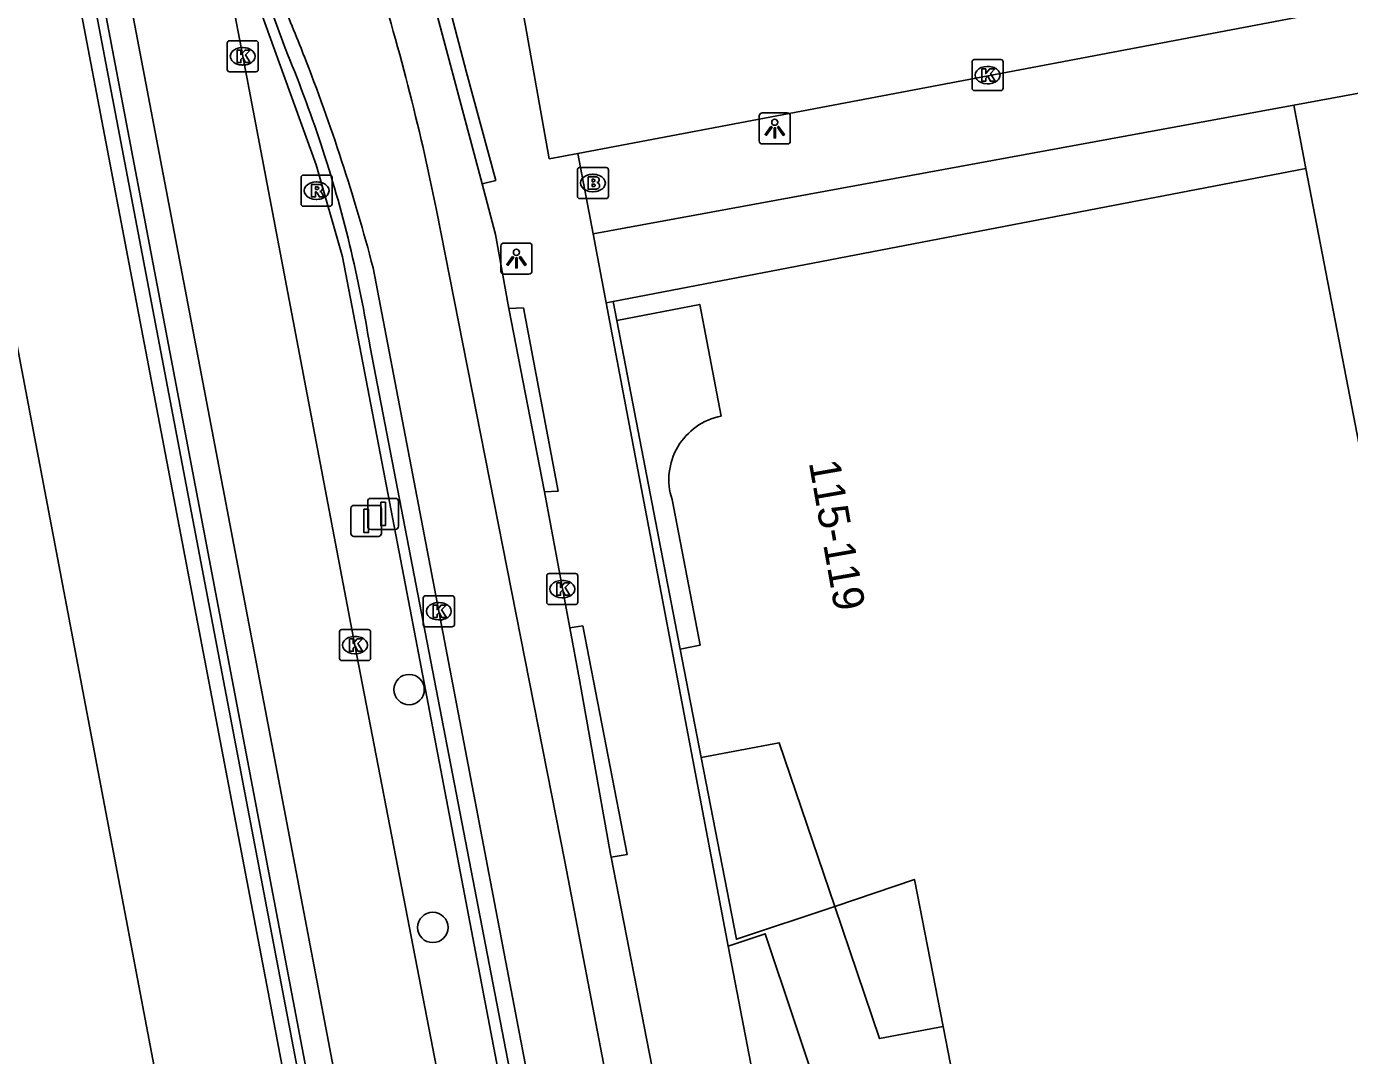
# Model space of a CAD drawing. Extents: x 159265 to 160143, y 383413 to 384319.
# Drawn here: x 159294.72 to 159337.31, y 383838.39 to 383871.52 of the extents above; entities that cross this region are included whole.
import ezdxf

# ---------------------------------------------------------------- set-up
doc = ezdxf.new("R2010")
doc.units = 0
for name, color, linetype in [('IMGEO_Boom', 7, 'Continuous'), ('IMGEO_Brandkraan', 7, 'Continuous'), ('IMGEO_Haag', 7, 'Continuous'), ('IMGEO_Kolk', 7, 'Continuous'), ('IMGEO_Lichtpunt', 7, 'Continuous'), ('IMGEO_Lijnafwatering', 7, 'Continuous'), ('IMGEO_Muur', 7, 'Continuous'), ('IMGEO_Pand', 7, 'Continuous'), ('IMGEO_Pand_nummerreeks', 7, 'Continuous'), ('IMGEO_Pand_overbouw', 7, 'Continuous'), ('IMGEO_Rijbaan_lokaal_gesloten', 7, 'Continuous'), ('IMGEO_Rijbaan_lokaal_open', 7, 'Continuous'), ('IMGEO_Rijbaan_regionaal_gesloten', 7, 'Continuous'), ('IMGEO_Rioolput', 7, 'Continuous'), ('IMGEO_Verkeersbordpaal', 7, 'Continuous'), ('IMGEO_Voetpad_open', 7, 'Continuous')]:
    doc.layers.add(name, color=color, linetype=linetype)

msp = doc.modelspace()

# ---------------------------------------------------------------- linework, layer by layer
at = {"layer": 'IMGEO_Boom'}
for centre in [(159307.041, 383850.169), (159307.803, 383842.511)]:
    msp.add_circle(centre, 0.489, dxfattribs=at)
at = {"layer": 'IMGEO_Brandkraan'}
for p, q in [((159312.456, 383866.053), (159312.456, 383866.905)), ((159312.531, 383866.979), (159313.383, 383866.979)), ((159313.457, 383866.905), (159313.457, 383866.053)), ((159312.944, 383866.759), (159312.969, 383866.759)), ((159313.383, 383865.979), (159312.531, 383865.979)), ((159312.967, 383866.199), (159312.942, 383866.199))]:
    msp.add_line(p, q, dxfattribs=at)
for points in [[(159312.456, 383866.053), (159312.456, 383866.905)], [(159312.531, 383866.979), (159313.383, 383866.979)], [(159313.457, 383866.905), (159313.457, 383866.053)], [(159312.804, 383866.679), (159312.804, 383866.279), (159313.017, 383866.279)], [(159313.035, 383866.679), (159312.804, 383866.679)], [(159312.983, 383866.598), (159312.929, 383866.598), (159312.929, 383866.522)], [(159312.929, 383866.522), (159312.982, 383866.522)], [(159312.991, 383866.446), (159312.929, 383866.446), (159312.929, 383866.365)], [(159313.383, 383865.979), (159312.531, 383865.979)], [(159312.929, 383866.365), (159312.991, 383866.365)]]:
    msp.add_lwpolyline(points, dxfattribs=at)
for centre, radius, start, end in [((159312.533, 383866.903), 0.0765, 91.552, 178.448), ((159312.533, 383866.903), 0.0765, 91.552, 178.448), ((159313.381, 383866.903), 0.0765, 1.552, 88.448), ((159313.381, 383866.903), 0.0765, 1.552, 88.448), ((159312.984, 383866.56), 0.0379, 267.8285, 90.9355), ((159312.992, 383866.405), 0.0404, 269.8759, 90.5077), ((159313.039, 383866.534), 0.145, 59.4692, 91.5367), ((159313.064, 383866.581), 0.0922, 285.5137, 58.1501), ((159313.069, 383866.389), 0.105, 301.3115, 78.989), ((159312.533, 383866.055), 0.0765, 181.552, 268.448), ((159312.533, 383866.055), 0.0765, 181.552, 268.448), ((159313.023, 383866.53), 0.251, 268.6676, 293.5347), ((159313.381, 383866.055), 0.0765, 271.552, 358.448), ((159313.381, 383866.055), 0.0765, 271.552, 358.448)]:
    msp.add_arc(centre, radius, start, end, dxfattribs=at)
for centre, major_axis, ratio, start_param, end_param in [((159312.943, 383866.479), (-0.387, 0.002), 0.722429, 4.712389, 7.853982), ((159312.968, 383866.479), (-0.39, 0.002), 0.717154, 1.570796, 4.712389)]:
    msp.add_ellipse(centre, major_axis=major_axis, ratio=ratio, start_param=start_param, end_param=end_param, dxfattribs=at)
at = {"layer": 'IMGEO_Haag'}
for points in [[(159303.045, 383870.823), (159301.691, 383874.543), (159301.384, 383874.434), (159304.05, 383867.063), (159304.897, 383864.099), (159307.114, 383852.521), (159310.388, 383835.369), (159314.42, 383814.315), (159315.234, 383809.973), (159313.799, 383809.591), (159322.047, 383766.911), (159322.585, 383766.955), (159315.649, 383810.084)], [(159315.649, 383810.084), (159305.782, 383861.189)]]:
    msp.add_lwpolyline(points, dxfattribs=at)
for centre, radius, start, end in [((159264.432, 383854.612), 41.878, 18.2647, 22.7741), ((159264.751, 383854.741), 41.535, 8.931, 18.2339)]:
    msp.add_arc(centre, radius, start, end, dxfattribs=at)
at = {"layer": 'IMGEO_Kolk'}
for p, q in [((159301.183, 383870.133), (159301.183, 383870.985)), ((159301.258, 383871.059), (159302.11, 383871.059)), ((159301.671, 383870.839), (159301.696, 383870.839)), ((159302.184, 383870.985), (159302.184, 383870.133)), ((159301.694, 383870.279), (159301.669, 383870.279)), ((159325.161, 383869.528), (159325.161, 383870.38)), ((159325.236, 383870.454), (159326.088, 383870.454)), ((159325.649, 383870.234), (159325.674, 383870.234)), ((159326.162, 383870.38), (159326.162, 383869.528)), ((159302.11, 383870.059), (159301.258, 383870.059)), ((159326.088, 383869.454), (159325.236, 383869.454)), ((159325.672, 383869.674), (159325.647, 383869.674)), ((159311.471, 383852.979), (159311.471, 383853.831)), ((159311.546, 383853.905), (159312.398, 383853.905)), ((159311.959, 383853.685), (159311.984, 383853.685)), ((159312.472, 383853.831), (159312.472, 383852.979)), ((159307.571, 383853.19), (159308.423, 383853.19)), ((159307.496, 383852.264), (159307.496, 383853.116)), ((159307.984, 383852.97), (159308.009, 383852.97)), ((159308.497, 383853.116), (159308.497, 383852.264)), ((159312.398, 383852.905), (159311.546, 383852.905)), ((159311.982, 383853.125), (159311.957, 383853.125)), ((159308.007, 383852.41), (159307.982, 383852.41)), ((159304.798, 383851.175), (159304.798, 383852.027)), ((159304.873, 383852.101), (159305.725, 383852.101)), ((159305.799, 383852.027), (159305.799, 383851.175)), ((159308.423, 383852.19), (159307.571, 383852.19)), ((159305.286, 383851.881), (159305.311, 383851.881)), ((159305.725, 383851.101), (159304.873, 383851.101)), ((159305.309, 383851.321), (159305.284, 383851.321))]:
    msp.add_line(p, q, dxfattribs=at)
for points in [[(159301.183, 383870.133), (159301.183, 383870.985)], [(159301.258, 383871.059), (159302.11, 383871.059)], [(159301.504, 383870.759), (159301.627, 383870.759), (159301.627, 383870.608), (159301.757, 383870.759), (159301.921, 383870.759), (159301.775, 383870.608), (159301.928, 383870.359), (159301.776, 383870.359), (159301.691, 383870.523), (159301.627, 383870.456), (159301.627, 383870.359), (159301.504, 383870.359), (159301.504, 383870.759)], [(159302.184, 383870.985), (159302.184, 383870.133)], [(159325.161, 383869.528), (159325.161, 383870.38)], [(159325.236, 383870.454), (159326.088, 383870.454)], [(159326.162, 383870.38), (159326.162, 383869.528)], [(159302.11, 383870.059), (159301.258, 383870.059)], [(159325.482, 383870.154), (159325.605, 383870.154), (159325.605, 383870.003), (159325.735, 383870.154), (159325.899, 383870.154), (159325.753, 383870.003), (159325.906, 383869.754), (159325.754, 383869.754), (159325.669, 383869.918), (159325.605, 383869.851), (159325.605, 383869.754), (159325.482, 383869.754), (159325.482, 383870.154)], [(159326.088, 383869.454), (159325.236, 383869.454)], [(159311.471, 383852.979), (159311.471, 383853.831)], [(159311.546, 383853.905), (159312.398, 383853.905)], [(159312.472, 383853.831), (159312.472, 383852.979)], [(159307.571, 383853.19), (159308.423, 383853.19)], [(159311.792, 383853.605), (159311.915, 383853.605), (159311.915, 383853.454), (159312.045, 383853.605), (159312.209, 383853.605), (159312.063, 383853.454), (159312.216, 383853.205), (159312.064, 383853.205), (159311.979, 383853.369), (159311.915, 383853.302), (159311.915, 383853.205), (159311.792, 383853.205), (159311.792, 383853.605)], [(159307.496, 383852.264), (159307.496, 383853.116)], [(159307.817, 383852.89), (159307.94, 383852.89), (159307.94, 383852.739), (159308.07, 383852.89), (159308.234, 383852.89), (159308.088, 383852.739), (159308.241, 383852.49), (159308.089, 383852.49), (159308.004, 383852.654), (159307.94, 383852.587), (159307.94, 383852.49), (159307.817, 383852.49), (159307.817, 383852.89)], [(159308.497, 383853.116), (159308.497, 383852.264)], [(159312.398, 383852.905), (159311.546, 383852.905)], [(159304.798, 383851.175), (159304.798, 383852.027)], [(159304.873, 383852.101), (159305.725, 383852.101)], [(159305.799, 383852.027), (159305.799, 383851.175)], [(159308.423, 383852.19), (159307.571, 383852.19)], [(159305.119, 383851.801), (159305.242, 383851.801), (159305.242, 383851.65), (159305.372, 383851.801), (159305.536, 383851.801), (159305.39, 383851.65), (159305.543, 383851.401), (159305.391, 383851.401), (159305.306, 383851.565), (159305.242, 383851.498), (159305.242, 383851.401), (159305.119, 383851.401), (159305.119, 383851.801)], [(159305.725, 383851.101), (159304.873, 383851.101)]]:
    msp.add_lwpolyline(points, dxfattribs=at)
for centre, start, end in [((159301.26, 383870.983), 91.552, 178.448), ((159301.26, 383870.983), 91.552, 178.448), ((159302.108, 383870.983), 1.552, 88.448), ((159302.108, 383870.983), 1.552, 88.448), ((159325.238, 383870.378), 91.552, 178.448), ((159325.238, 383870.378), 91.552, 178.448), ((159326.086, 383870.378), 1.552, 88.448), ((159326.086, 383870.378), 1.552, 88.448), ((159301.26, 383870.135), 181.552, 268.448), ((159301.26, 383870.135), 181.552, 268.448), ((159302.108, 383870.135), 271.552, 358.448), ((159302.108, 383870.135), 271.552, 358.448), ((159325.238, 383869.53), 181.552, 268.448), ((159325.238, 383869.53), 181.552, 268.448), ((159326.086, 383869.53), 271.552, 358.448), ((159326.086, 383869.53), 271.552, 358.448), ((159311.548, 383853.829), 91.552, 178.448), ((159311.548, 383853.829), 91.552, 178.448), ((159312.396, 383853.829), 1.552, 88.448), ((159312.396, 383853.829), 1.552, 88.448), ((159307.573, 383853.114), 91.552, 178.448), ((159307.573, 383853.114), 91.552, 178.448), ((159308.421, 383853.114), 1.552, 88.448), ((159308.421, 383853.114), 1.552, 88.448), ((159311.548, 383852.981), 181.552, 268.448), ((159311.548, 383852.981), 181.552, 268.448), ((159312.396, 383852.981), 271.552, 358.448), ((159312.396, 383852.981), 271.552, 358.448), ((159304.875, 383852.025), 91.552, 178.448), ((159304.875, 383852.025), 91.552, 178.448), ((159305.723, 383852.025), 1.552, 88.448), ((159305.723, 383852.025), 1.552, 88.448), ((159307.573, 383852.266), 181.552, 268.448), ((159307.573, 383852.266), 181.552, 268.448), ((159308.421, 383852.266), 271.552, 358.448), ((159308.421, 383852.266), 271.552, 358.448), ((159304.875, 383851.177), 181.552, 268.448), ((159304.875, 383851.177), 181.552, 268.448), ((159305.723, 383851.177), 271.552, 358.448), ((159305.723, 383851.177), 271.552, 358.448)]:
    msp.add_arc(centre, 0.0765, start, end, dxfattribs=at)
for centre, major_axis, ratio, start_param, end_param in [((159301.67, 383870.559), (-0.387, 0.002), 0.722429, 4.712389, 7.853982), ((159301.695, 383870.559), (-0.39, 0.002), 0.717154, 1.570796, 4.712389), ((159325.648, 383869.954), (-0.387, 0.002), 0.722429, 4.712389, 7.853982), ((159325.673, 383869.954), (-0.39, 0.002), 0.717154, 1.570796, 4.712389), ((159311.958, 383853.405), (-0.387, 0.002), 0.722429, 4.712389, 7.853982), ((159311.983, 383853.405), (-0.39, 0.002), 0.717154, 1.570796, 4.712389), ((159307.983, 383852.69), (-0.387, 0.002), 0.722429, 4.712389, 7.853982), ((159308.008, 383852.69), (-0.39, 0.002), 0.717154, 1.570796, 4.712389), ((159305.285, 383851.601), (-0.387, 0.002), 0.722429, 4.712389, 7.853982), ((159305.31, 383851.601), (-0.39, 0.002), 0.717154, 1.570796, 4.712389)]:
    msp.add_ellipse(centre, major_axis=major_axis, ratio=ratio, start_param=start_param, end_param=end_param, dxfattribs=at)
at = {"layer": 'IMGEO_Lichtpunt'}
for p, q in [((159318.313, 383868.639), (159318.313, 383867.832)), ((159318.313, 383868.639), (159318.313, 383867.832)), ((159319.215, 383868.734), (159318.407, 383868.734)), ((159319.215, 383868.734), (159318.407, 383868.734)), ((159319.309, 383867.832), (159319.309, 383868.639)), ((159319.309, 383867.832), (159319.309, 383868.639)), ((159318.407, 383867.738), (159319.215, 383867.738)), ((159318.407, 383867.738), (159319.215, 383867.738)), ((159309.997, 383864.45), (159309.997, 383863.643)), ((159309.997, 383864.45), (159309.997, 383863.643)), ((159310.899, 383864.545), (159310.091, 383864.545)), ((159310.899, 383864.545), (159310.091, 383864.545)), ((159310.993, 383863.643), (159310.993, 383864.45)), ((159310.993, 383863.643), (159310.993, 383864.45)), ((159310.091, 383863.549), (159310.899, 383863.549)), ((159310.091, 383863.549), (159310.899, 383863.549))]:
    msp.add_line(p, q, dxfattribs=at)
for points in [[(159318.687, 383868.303), (159318.726, 383868.275), (159318.538, 383868.013), (159318.5, 383868.04), (159318.687, 383868.303)], [(159318.789, 383868.255), (159318.836, 383868.255), (159318.836, 383867.933), (159318.789, 383867.933), (159318.789, 383868.255)], [(159318.899, 383868.275), (159318.937, 383868.302), (159319.124, 383868.04), (159319.085, 383868.012), (159318.899, 383868.275)], [(159310.371, 383864.114), (159310.41, 383864.086), (159310.222, 383863.824), (159310.184, 383863.851), (159310.371, 383864.114)], [(159310.473, 383864.066), (159310.52, 383864.066), (159310.52, 383863.744), (159310.473, 383863.744), (159310.473, 383864.066)], [(159310.583, 383864.086), (159310.621, 383864.113), (159310.808, 383863.851), (159310.769, 383863.823), (159310.583, 383864.086)]]:
    msp.add_lwpolyline(points, dxfattribs=at)
for centre in [(159318.812, 383868.437), (159310.496, 383864.248)]:
    msp.add_circle(centre, 0.0994, dxfattribs=at)
for centre, start, end in [((159318.407, 383868.639), 90, 180), ((159318.407, 383868.639), 90, 180), ((159319.215, 383868.639), 0, 90), ((159319.215, 383868.639), 0, 90), ((159318.407, 383867.832), 180, 270), ((159318.407, 383867.832), 180, 270), ((159319.215, 383867.832), 270, 0), ((159319.215, 383867.832), 270, 360), ((159310.091, 383864.45), 90, 180), ((159310.091, 383864.45), 90, 180), ((159310.899, 383864.45), 0, 90), ((159310.899, 383864.45), 0, 90), ((159310.091, 383863.643), 180, 270), ((159310.091, 383863.643), 180, 270), ((159310.899, 383863.643), 270, 0), ((159310.899, 383863.643), 270, 360)]:
    msp.add_arc(centre, 0.0946, start, end, dxfattribs=at)
at = {"layer": 'IMGEO_Lijnafwatering'}
for points in [[(159294.994, 383879.804), (159298.74, 383860.158)], [(159298.74, 383860.158), (159302.502, 383840.43)], [(159302.502, 383840.43), (159306.23, 383820.728)]]:
    msp.add_lwpolyline(points, dxfattribs=at)
at = {"layer": 'IMGEO_Muur'}
for points in [[(159314.238, 383781.271), (159280.741, 383957.112), (159281.061, 383957.173)], [(159281.061, 383957.173), (159314.487, 383781.303), (159314.238, 383781.271)], [(159317.314, 383841.912), (159318.502, 383842.307), (159321.31, 383833.897), (159319.669, 383833.551), (159321.634, 383823.314), (159326.463, 383824.191), (159326.544, 383823.626), (159321.047, 383822.509)], [(159321.047, 383822.509), (159317.314, 383841.912)]]:
    msp.add_lwpolyline(points, dxfattribs=at)
at = {"layer": 'IMGEO_Pand'}
for points in [[(159313.609, 383862.665), (159335.903, 383866.948)], [(159335.903, 383866.948), (159341.456, 383838.196), (159325.065, 383835.022), (159324.228, 383839.323)], [(159313.726, 383862.057), (159313.609, 383862.665)], [(159313.726, 383862.057), (159316.397, 383862.572), (159317.085, 383858.975)], [(159315.504, 383856.284), (159316.414, 383851.6), (159315.769, 383851.474)], [(159320.743, 383843.189), (159318.948, 383848.455), (159316.444, 383847.985), (159315.769, 383851.474)], [(159320.743, 383843.189), (159323.306, 383844.057), (159324.228, 383839.323)]]:
    msp.add_lwpolyline(points, dxfattribs=at)
msp.add_arc((159317.489, 383856.928), 2.087, 101.168, 197.9624, dxfattribs=at)
at = {"layer": 'IMGEO_Pand_overbouw'}
for points in [[(159317.085, 383858.975), (159316.397, 383862.572), (159313.726, 383862.057), (159315.769, 383851.474)], [(159315.769, 383851.474), (159316.414, 383851.6), (159315.504, 383856.284)]]:
    msp.add_lwpolyline(points, dxfattribs=at)
msp.add_lwpolyline([(159316.444, 383847.985), (159317.577, 383842.129), (159320.743, 383843.189), (159318.948, 383848.455)], close=True, dxfattribs=at)
msp.add_arc((159317.489, 383856.928), 2.087, 101.168, 197.9624, dxfattribs=at)
at = {"layer": 'IMGEO_Rijbaan_lokaal_gesloten'}
for points in [[(159309.389, 383866.455), (159307.656, 383872.978)], [(159310.248, 383862.443), (159309.824, 383864.824), (159309.389, 383866.455)], [(159307.922, 383865.606), (159312.048, 383844.632), (159316.297, 383822.528)], [(159311.396, 383856.537), (159310.248, 383862.443)], [(159312.211, 383852.157), (159311.396, 383856.537)], [(159313.541, 383844.77), (159313.522, 383844.866), (159312.523, 383850.482), (159312.211, 383852.157)], [(159317.816, 383822.853), (159313.541, 383844.77)]]:
    msp.add_lwpolyline(points, dxfattribs=at)
msp.add_arc((159231.175, 383850.119), 78.294, 11.40866, 17.43982, dxfattribs=at)
at = {"layer": 'IMGEO_Rijbaan_lokaal_open'}
for points in [[(159310.508, 383873.119), (159311.553, 383867.258), (159312.476, 383867.433)], [(159336.505, 383871.985), (159312.476, 383867.433)], [(159342.623, 383870.295), (159335.525, 383868.99)], [(159335.903, 383866.948), (159335.525, 383868.99)], [(159305.88, 383863.75), (159307.998, 383852.69), (159311.272, 383835.538), (159315.304, 383814.483), (159316.083, 383810.325), (159316.588, 383807.359), (159317.424, 383802.205), (159320.139, 383784.999), (159322.954, 383766.957)], [(159313.382, 383862.621), (159313.609, 383862.665)], [(159313.382, 383862.621), (159317.314, 383841.912)], [(159315.769, 383851.474), (159313.726, 383862.057)], [(159324.228, 383839.323), (159322.184, 383838.933), (159320.743, 383843.189)]]:
    msp.add_lwpolyline(points, dxfattribs=at)
for centre, radius, start, end in [((159244.082, 383847.239), 63.982, 21.3924, 23.23455), ((159246.013, 383848.023), 61.899, 14.71884, 21.36879)]:
    msp.add_arc(centre, radius, start, end, dxfattribs=at)
at = {"layer": 'IMGEO_Rijbaan_regionaal_gesloten'}
for points in [[(159280.211, 384172.631), (159274.487, 384158.497), (159272.013, 384150.923), (159269.535, 384141.678), (159267.507, 384132.324), (159266.005, 384119.851), (159265.496, 384109.233), (159267.965, 384029.162), (159271.62, 383998.252), (159277.018, 383952.804), (159311.634, 383770.65), (159326.117, 383701.416), (159334.862, 383664.196)], [(159316.213, 383777.09), (159315.456, 383780.799), (159309.353, 383813.036), (159303.32, 383844.753), (159290.389, 383912.552), (159284.239, 383944.948), (159283.058, 383951.058), (159282.172, 383957.025)], [(159300.668, 383875.89), (159301.684, 383870.559), (159305.298, 383851.601), (159308.807, 383833.455), (159312.065, 383816.27), (159313.356, 383809.503), (159318.245, 383783.881), (159321.342, 383767.668), (159321.513, 383766.682)]]:
    msp.add_lwpolyline(points, dxfattribs=at)
at = {"layer": 'IMGEO_Rioolput'}
for p, q in [((159303.561, 383865.807), (159303.561, 383866.659)), ((159303.636, 383866.733), (159304.488, 383866.733)), ((159304.049, 383866.513), (159304.074, 383866.513)), ((159304.562, 383866.659), (159304.562, 383865.807)), ((159304.488, 383865.733), (159303.636, 383865.733)), ((159304.072, 383865.953), (159304.047, 383865.953))]:
    msp.add_line(p, q, dxfattribs=at)
for points in [[(159303.561, 383865.807), (159303.561, 383866.659)], [(159303.636, 383866.733), (159304.488, 383866.733)], [(159304.15, 383866.431), (159303.898, 383866.433), (159303.898, 383866.033)], [(159304.562, 383866.659), (159304.562, 383865.807)], [(159303.898, 383866.033), (159304.022, 383866.033), (159304.022, 383866.195), (159304.033, 383866.195)], [(159304.076, 383866.352), (159304.022, 383866.352), (159304.022, 383866.271)], [(159304.022, 383866.271), (159304.074, 383866.271)], [(159304.08, 383866.166), (159304.151, 383866.033), (159304.291, 383866.033), (159304.226, 383866.159)], [(159304.488, 383865.733), (159303.636, 383865.733)]]:
    msp.add_lwpolyline(points, dxfattribs=at)
for centre, radius, start, end in [((159303.638, 383866.657), 0.0765, 91.552, 178.448), ((159303.638, 383866.657), 0.0765, 91.552, 178.448), ((159304.149, 383866.321), 0.109, 350.3612, 89.416), ((159304.486, 383866.657), 0.0765, 1.552, 88.448), ((159304.486, 383866.657), 0.0765, 1.552, 88.448), ((159304.032, 383866.142), 0.0533, 26.0293, 88.6989), ((159304.058, 383866.46), 0.19, 274.7715, 282.9687), ((159304.082, 383866.256), 0.0964, 77.0061, 93.1865), ((159304.096, 383866.313), 0.0378, 276.6634, 79.6772), ((159304.147, 383866.321), 0.112, 277.5842, 350.9817), ((159304.131, 383866.106), 0.108, 29.5134, 73.7905), ((159303.638, 383865.809), 0.0765, 181.552, 268.448), ((159303.638, 383865.809), 0.0765, 181.552, 268.448), ((159304.486, 383865.809), 0.0765, 271.552, 358.448), ((159304.486, 383865.809), 0.0765, 271.552, 358.448)]:
    msp.add_arc(centre, radius, start, end, dxfattribs=at)
for centre, major_axis, ratio, start_param, end_param in [((159304.048, 383866.233), (-0.387, 0.002), 0.722429, 4.712389, 7.853982), ((159304.073, 383866.233), (-0.39, 0.002), 0.717154, 1.570796, 4.712389)]:
    msp.add_ellipse(centre, major_axis=major_axis, ratio=ratio, start_param=start_param, end_param=end_param, dxfattribs=at)
at = {"layer": 'IMGEO_Verkeersbordpaal'}
for p, q in [((159305.706, 383855.426), (159305.706, 383856.226)), ((159305.706, 383856.226), (159305.706, 383855.426)), ((159305.806, 383856.326), (159306.596, 383856.326)), ((159306.596, 383856.326), (159305.806, 383856.326)), ((159306.696, 383856.226), (159306.696, 383855.426)), ((159306.696, 383855.426), (159306.696, 383856.226)), ((159305.163, 383855.199), (159305.163, 383855.999)), ((159305.163, 383855.999), (159305.163, 383855.199)), ((159305.263, 383856.099), (159306.053, 383856.099)), ((159306.053, 383856.099), (159305.263, 383856.099)), ((159306.153, 383855.999), (159306.153, 383855.199)), ((159306.153, 383855.199), (159306.153, 383855.999)), ((159306.596, 383855.326), (159305.806, 383855.326)), ((159305.806, 383855.326), (159306.596, 383855.326)), ((159306.053, 383855.099), (159305.263, 383855.099)), ((159305.263, 383855.099), (159306.053, 383855.099))]:
    msp.add_line(p, q, dxfattribs=at)
for points in [[(159306.126, 383856.201), (159306.276, 383856.201), (159306.276, 383855.451), (159306.126, 383855.451), (159306.126, 383856.201)], [(159305.583, 383855.974), (159305.733, 383855.974), (159305.733, 383855.224), (159305.583, 383855.224), (159305.583, 383855.974)]]:
    msp.add_lwpolyline(points, dxfattribs=at)
for centre, start, end in [((159305.806, 383856.226), 90, 180), ((159305.806, 383856.226), 90, 180), ((159306.596, 383856.226), 0, 90), ((159306.596, 383856.226), 360, 90), ((159305.263, 383855.999), 90, 180), ((159305.263, 383855.999), 90, 180), ((159306.053, 383855.999), 0, 90), ((159306.053, 383855.999), 360, 90), ((159305.806, 383855.426), 180, 270), ((159305.806, 383855.426), 180, 270), ((159306.596, 383855.426), 270, 0), ((159306.596, 383855.426), 270, 0), ((159305.263, 383855.199), 180, 270), ((159305.263, 383855.199), 180, 270), ((159306.053, 383855.199), 270, 0), ((159306.053, 383855.199), 270, 0)]:
    msp.add_arc(centre, 0.1, start, end, dxfattribs=at)
at = {"layer": 'IMGEO_Voetpad_open'}
for points in [[(159308.096, 383873.084), (159308.887, 383870.04), (159309.827, 383866.555), (159309.389, 383866.455)], [(159335.525, 383868.99), (159312.96, 383864.841)], [(159312.476, 383867.433), (159312.96, 383864.841)], [(159312.96, 383864.841), (159313.382, 383862.621)], [(159310.248, 383862.443), (159310.72, 383862.457), (159311.834, 383856.559), (159311.396, 383856.537)], [(159312.211, 383852.157), (159312.628, 383852.221), (159314.061, 383844.86), (159313.541, 383844.77)]]:
    msp.add_lwpolyline(points, dxfattribs=at)

# ---------------------------------------------------------------- texts
at = {"layer": 'IMGEO_Pand_nummerreeks'}
msp.add_text('115-119', height=1, rotation=279.9453, dxfattribs=at).set_placement((159319.905, 383857.483))

doc.saveas('drawing.dxf')
